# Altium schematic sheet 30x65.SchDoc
size A4
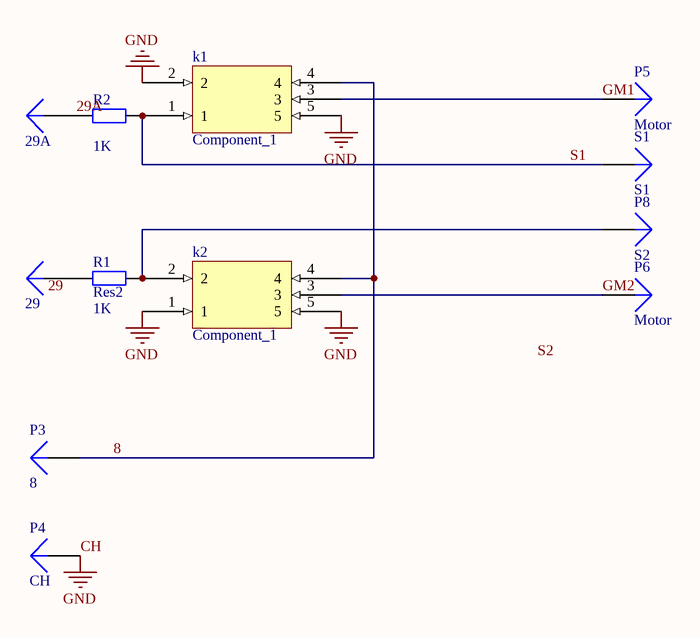
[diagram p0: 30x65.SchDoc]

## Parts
k1  Component_1  [PCBComponent_1]
k2  Component_1  [PCBComponent_1]
P1  29A  [PIN1]
P2  29  [PIN1]
P3  8  [PIN1]
P4  CH  [PIN1]
P5  Motor  [PIN1]
P6  Motor  [PIN1]
P8  S2  [PIN1]
R1  Res2  value 1K  [AXIAL-0.7]
R2  value 1K  [AXIAL-0.7]  (hidden comment: Res2)
S1  S1  [PIN1]

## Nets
CH: k1.2 k1.5 k2.1 k2.5 P4.1  [also labelled GND]
8: k1.4 k2.4 P3.1
29A: P1.1 R2.1
GM1: k1.3 P5.1
GM2: k2.3 P6.1
S1: k1.1 R2.2 S1.1
Netk2_2: k2.2 P8.1 R1.2
NetP2_1: P2.1 R1.1

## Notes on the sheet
- Labels drawn without touching a wire or pin: 29, S2

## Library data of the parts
P1-P6 P8 S1 = Plug
R1 R2 = Res2: Resistor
